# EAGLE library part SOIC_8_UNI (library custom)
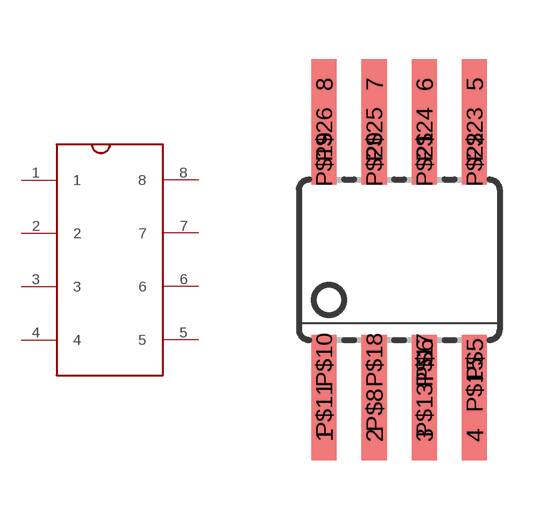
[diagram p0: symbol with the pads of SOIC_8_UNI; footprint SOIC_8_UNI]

Designator prefix -

## SOIC_8_UNI  [SOIC_8_UNI]
1  1
2  2
3  3
4  4
5  5
6  6
7  7
8  8

## Footprint SOIC_8_UNI (pad centres in mm)
Small Outline Package
smd 0.635 x 1.27: 1 -1.905,-4.445; 2 -0.635,-4.445; 3 0.635,-4.445; 4 1.905,-4.445; 5 1.905,4.445; 6 0.635,4.445; 7 -0.635,4.445; 8 -1.905,4.445; P$5 1.905,-2.54; P$6 0.635,-2.54; P$8 -0.635,-3.81; P$10 -1.905,-2.54; P$11 -1.905,-3.81; P$13 0.635,-3.81; P$15 1.905,-3.175; P$17 0.635,-2.54; P$18 -0.635,-2.54; P$19 -1.905,2.54; P$20 -0.635,2.54; P$21 0.635,2.54; P$22 1.905,2.54; P$23 1.905,3.175; P$24 0.635,3.175; P$25 -0.635,3.175; P$26 -1.905,3.175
